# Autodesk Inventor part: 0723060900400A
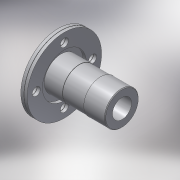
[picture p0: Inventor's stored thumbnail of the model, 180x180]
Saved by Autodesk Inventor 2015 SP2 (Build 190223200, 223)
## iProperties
Created: 2017-02
Part Number: 0723060900400A
Material: PVC-Piping
Description: PLASSON FLANGE ADAPTOR WITH METAL FLANGE 90-4"
Document SubType Name: Modeling
Designer: KIM
Mass: 92.6774 g
Surface Area: 199.44 cm^2
Volume: 66.1981 cm^3
Density: 1.4 g/cm^3
Appearance: Smooth - White
Author: Кирилл
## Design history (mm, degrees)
derived "872306.ipt"
feature "Solid1::872306.ipt"
tag "TaggingFeature1"
body "Solid1"
other parameters: "d73" = 17.5, "d74" = 90 deg, "d75" = 0.3, "d77" = 18, "d80" = 0, "d82" = 360 deg, "d96" = 0.3, "d99" = 360 deg, "d103" = 175, "d104" = 1.8, "d107" = 117, "d108" = 4.375, "d116" = 88.2, "d117" = 58.33333, "d118" = 58.33333, "d120" = 10.8, "H_" = 175, "S_" = 18
